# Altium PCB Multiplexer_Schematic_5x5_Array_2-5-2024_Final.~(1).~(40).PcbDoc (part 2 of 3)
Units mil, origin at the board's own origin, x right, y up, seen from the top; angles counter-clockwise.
Board outline 7305 x 4000 mil, 8 copper layers (Loop Shield 1, Loop Trace, Loop Shield 2, GND 1, DC Signal 1, DC Signal 2, GND 2 (RF), RF), stack 74.018 mil thick; 89 components, 122 nets, 436 pads, 3654 vias.
Unrouted connection lines stored in the file: 2.
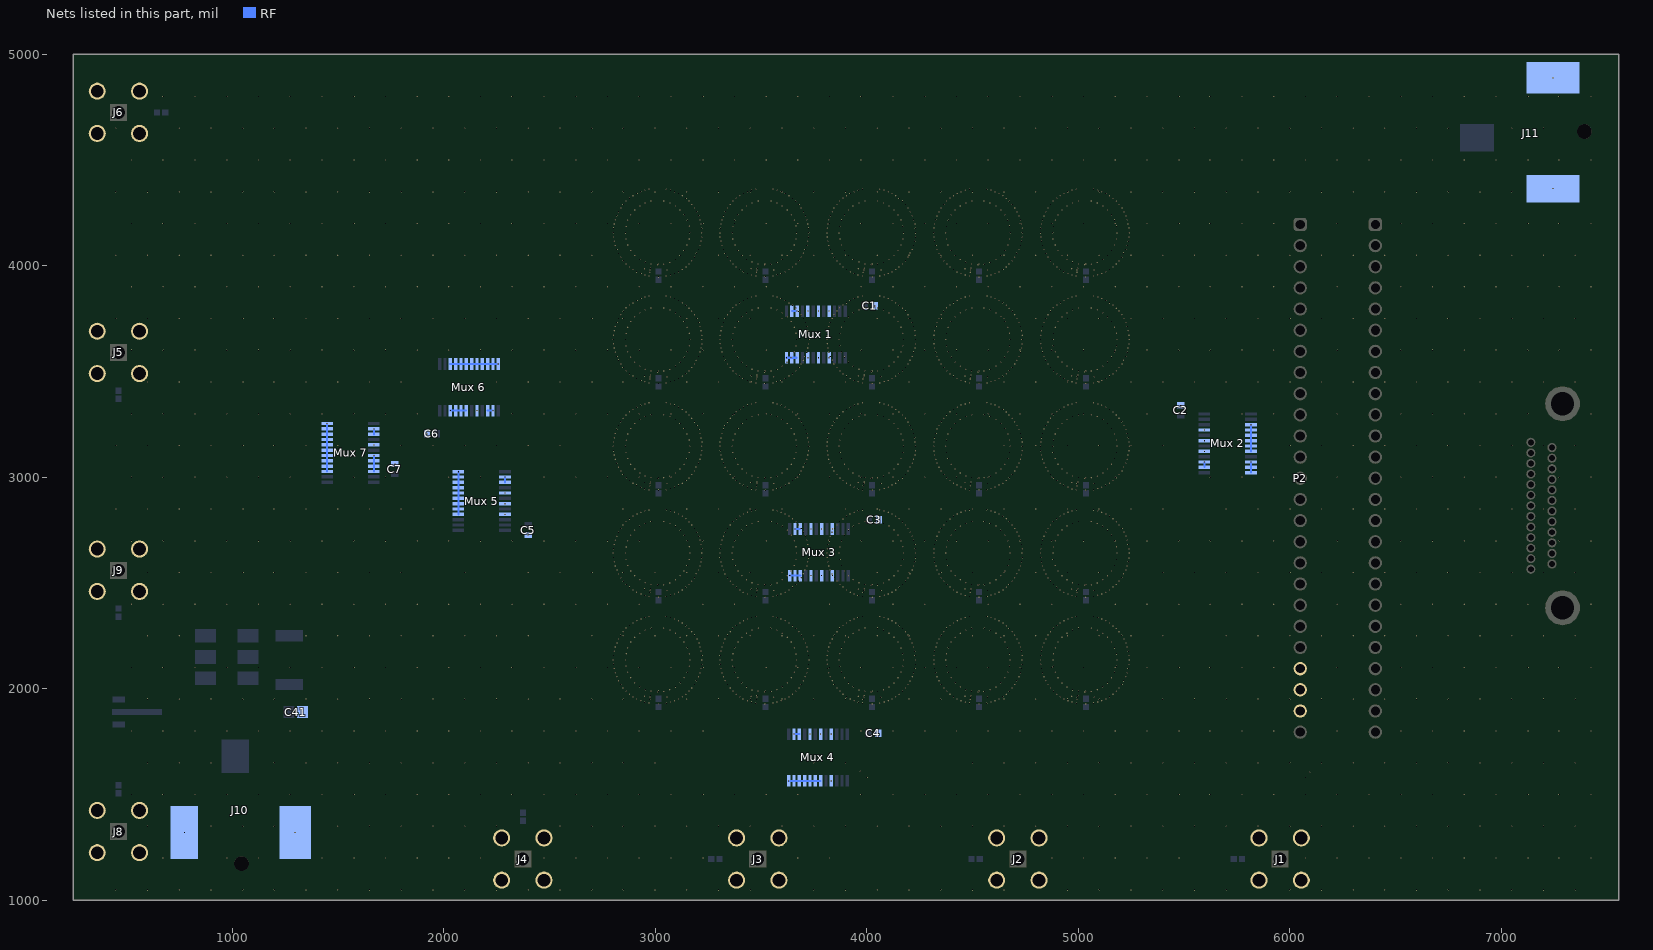
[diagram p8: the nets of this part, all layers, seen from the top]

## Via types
v1: diameter 6, hole 4, Loop Shield 1 to Loop Shield 2, 2300 vias
v2: diameter 6, hole 4, GND 2 (RF) to RF, 1131 vias
v3: diameter 6, hole 4, Loop Shield 2 to RF, 75 vias
v4: diameter 6, hole 4, DC Signal 1 to DC Signal 2, 57 vias
v5: diameter 6, hole 4, DC Signal 1 to RF, 25 vias
v6: diameter 6, hole 4, Loop Shield 2 to GND 2 (RF), 25 vias
v7: diameter 6, hole 4, Loop Trace to RF, 25 vias
v8: diameter 6, hole 4, DC Signal 2 to RF, 16 vias

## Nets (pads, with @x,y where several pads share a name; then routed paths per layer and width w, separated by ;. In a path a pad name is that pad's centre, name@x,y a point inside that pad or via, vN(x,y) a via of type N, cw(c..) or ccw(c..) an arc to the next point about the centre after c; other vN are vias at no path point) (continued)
GND: "Mux 1.2" "Mux 1.3" "Mux 1.5" "Mux 1.7" "Mux 1.9" "Mux 1.16" "Mux 1.18" "Mux 1.20" "Mux 1.22" "Mux 1.23" "Mux 1.24" "Mux 2.2" "Mux 2.3" "Mux 2.5" "Mux 2.7" "Mux 2.9" "Mux 2.15" "Mux 2.16" "Mux 2.17" "Mux 2.18" "Mux 2.19" "Mux 2.20" "Mux 2.22" "Mux 2.23" "Mux 2.24" "Mux 3.2" "Mux 3.3" "Mux 3.5" "Mux 3.7" "Mux 3.9" "Mux 3.16" "Mux 3.18" "Mux 3.20" "Mux 3.22" "Mux 3.23" "Mux 3.24" "Mux 4.2" "Mux 4.3" "Mux 4.5" "Mux 4.7" "Mux 4.9" "Mux 4.16" "Mux 4.18" "Mux 4.19" "Mux 4.20" "Mux 4.21" "Mux 4.22" "Mux 4.23" "Mux 4.24" "Mux 5.2" "Mux 5.3" "Mux 5.5" "Mux 5.7" "Mux 5.9" "Mux 5.16" "Mux 5.17" "Mux 5.18" "Mux 5.19" "Mux 5.20" "Mux 5.21" "Mux 5.22" "Mux 5.23" "Mux 5.24" "Mux 6.2" "Mux 6.3" "Mux 6.5" "Mux 6.7" "Mux 6.8" "Mux 6.9" "Mux 6.10" "Mux 6.15" "Mux 6.16" "Mux 6.17" "Mux 6.18" "Mux 6.19" "Mux 6.20" "Mux 6.21" "Mux 6.22" "Mux 6.23" "Mux 6.24" "Mux 7.2" "Mux 7.3" "Mux 7.5" "Mux 7.7" "Mux 7.8" "Mux 7.9" "Mux 7.10" "Mux 7.15" "Mux 7.16" "Mux 7.17" "Mux 7.18" "Mux 7.19" "Mux 7.20" "Mux 7.21" "Mux 7.22" "Mux 7.23" "Mux 7.24" C1.2 C2.2 C3.2 C4.2 C5.2 C6.2 C7.2 C41.2 J1.2 J1.3 J1.4 J1.5 J2.2 J2.3 J2.4 J2.5 J3.2 J3.3 J3.4 J3.5 J4.2 J4.3 J4.4 J4.5 J5.2 J5.3 J5.4 J5.5 J6.2 J6.3 J6.4 J6.5 J8.2 J8.3 J8.4 J8.5 J9.2 J9.3 J9.4 J9.5 J10.2 J10.3 J11.2 J11.3 P2.22 P2.23 P2.24 | length 1402
  RF w10: 1449.76,3026.81 1449.76,3052.01 1449.76,3077.2 1449.76,3102.4 1449.76,3127.6 1449.76,3152.8 1449.76,3177.99 1449.76,3203.19 1449.76,3228.39 v2(1449.76,3253.58) ; 1670.24,3026.81 1670.24,3052.01 1670.24,3077.2 v2(1670.24,3102.4) ; 1670.24,3203.19 v2(1670.24,3228.39) ; v2(2031.81,3314.76) 2057.01,3314.76 2082.2,3314.76 2106.8,3314.76 ; 2031.81,3535.24 2057.01,3535.24 2082.2,3535.24 2107.4,3535.24 2132.6,3535.24 2157.8,3535.24 2182.99,3535.24 2208.19,3535.24 2233.39,3535.24 v2@2258.58,3535.24 ; 2069.76,2824.38 2069.76,2849.58 2069.76,2874.77 2069.76,2899.97 2069.76,2925.17 2069.76,2950.36 2069.76,2975.56 2069.76,3000.76 v2(2069.76,3025.95) ; 2208.19,3314.76 v2(2233.39,3314.76) ; 2290.24,2975.56 v2(2290.24,3000.76) ; v2(3621.42,3564.76) 3646.61,3564.76 3668.94,3564.76 ; v2(3631.42,1564.76) 3656.61,1564.76 3681.81,1564.76 3707.01,1564.76 3732.2,1564.76 3757.4,1564.76 3782.6,1564.76 ; v2(3636.42,2534.76) 3661.61,2534.76 3686.81,2534.76 ; 3646.61,3785.24 3671.37,3785.24 v2(3671.65,3785.52) ; v2@3658.62,1785.24 3681.81,1785.24 ; v2(3661.61,2755.24) 3683.94,2755.24 ; v2@5595,3070.34 cw(c5596.47,3070.34) v2(5596.47,3071.81) 5596.47,3049.49 ; 5816.94,3021.42 5816.94,3046.61 v2(5816.94,3071.81) ; 5816.94,3122.2 5816.94,3147.4 5816.94,3172.6 5816.94,3197.8 5816.94,3222.99 v2(5816.94,3248.19)
  other v1: 2970.86,1930.81 3052.58,1930.81 3475.86,1930.81 3557.58,1930.81 3980.86,1930.81 4062.58,1930.81 4485.86,1930.81 4567.58,1930.81 4990.86,1930.81 5072.58,1930.81 2950.93,1935.81 3455.93,1935.81 3960.93,1935.81 4465.93,1935.81 4970.93,1935.81 3073.01,1937.21 3578.01,1937.21 4083.01,1937.21 4588.01,1937.21 5093.01,1937.21 2931.57,1942.73 3091.87,1942.73 3436.57,1942.73 3596.87,1942.73 3941.57,1942.73 4101.87,1942.73 4446.57,1942.73 4606.87,1942.73 4951.57,1942.73 5111.87,1942.73 2974.61,1949.63 3479.61,1949.63 3984.61,1949.63 4489.61,1949.63 4994.61,1949.63 2911.98,1951.64 3110.45,1951.52 3416.98,1951.64 3615.45,1951.52 3921.98,1951.64 4120.45,1951.52 4426.98,1951.64 4625.45,1951.52 4931.98,1951.64 5130.45,1951.52 2895.37,1962.08 3128.08,1962.08 3400.37,1962.08 3633.08,1962.08 3905.37,1962.08 4138.08,1962.08 4410.37,1962.08 4643.08,1962.08 4915.37,1962.08 5148.08,1962.08 2950,1965 3455,1965 3960,1965 4465,1965 4970,1965 2978.23,1967.83 3483.23,1967.83 3988.23,1967.83 4493.23,1967.83 4998.23,1967.83 2878.86,1974.33 3144.58,1974.33 3383.86,1974.33 3649.58,1974.33 3888.86,1974.33 4154.58,1974.33 4393.86,1974.33 4659.58,1974.33 4898.86,1974.33 5164.58,1974.33 3011.72,1984.11 3516.72,1984.11 4021.72,1984.11 4526.72,1984.11 5031.72,1984.11 3041.4,1987.04 3546.4,1987.04 4051.4,1987.04 4556.4,1987.04 5061.4,1987.04 2863.63,1988.13 2981.13,1988.15 3159.81,1988.13 3368.63,1988.13 3486.13,1988.15 3664.81,1988.13 3873.63,1988.13 3991.13,1988.15 4169.81,1988.13 4378.63,1988.13 4496.13,1988.15 4674.81,1988.13 4883.63,1988.13 5001.13,1988.15 5179.81,1988.13 3069.84,1994.62 3574.84,1994.62 4079.84,1994.62 4584.84,1994.62 5089.84,1994.62 2953.51,1995.69 3458.51,1995.69 3963.51,1995.69 4468.51,1995.69 4973.51,1995.69 2849.83,2003.36 3173.61,2003.36 3354.83,2003.36 3678.61,2003.36 3859.83,2003.36 4183.61,2003.36 4364.83,2003.36 4688.61,2003.36 4869.83,2003.36 5193.61,2003.36 2927.21,2009.75 3096.23,2009.75 3432.21,2009.75 3601.23,2009.75 3937.21,2009.75 4106.23,2009.75 4442.21,2009.75 4611.23,2009.75 4947.21,2009.75 5116.23,2009.75 2837.58,2019.87 3185.86,2019.87 3342.58,2019.87 3690.86,2019.87 3847.58,2019.87 4195.86,2019.87 4352.58,2019.87 4700.86,2019.87 4857.58,2019.87 5205.86,2019.87 2904.17,2028.67 3119.28,2028.67 3409.17,2028.67 3624.28,2028.67 3914.17,2028.67 4129.28,2028.67 4419.17,2028.67 4634.28,2028.67 4924.17,2028.67 5139.28,2028.67 2827.02,2037.49 3332.02,2037.49 3837.02,2037.49 4342.02,2037.49 4847.02,2037.49 3194.83,2038.24 3699.83,2038.24 4204.83,2038.24 4709.83,2038.24 5214.83,2038.24 2885.25,2051.71 3138.19,2051.71 3390.25,2051.71 3643.19,2051.71 3895.25,2051.71 4148.19,2051.71 4400.25,2051.71 4653.19,2051.71 4905.25,2051.71 5158.19,2051.71 2818.23,2056.07 3205.21,2056.07 3323.23,2056.07 3710.21,2056.07 3828.23,2056.07 4215.21,2056.07 4333.23,2056.07 4720.21,2056.07 4838.23,2056.07 5225.21,2056.07 2811.31,2075.43 3212.14,2075.43 3316.31,2075.43 3717.14,2075.43 3821.31,2075.43 4222.14,2075.43 4326.31,2075.43 4727.14,2075.43 4831.31,2075.43 5232.14,2075.43 2871.19,2078.01 3152.25,2078.01 3376.19,2078.01 3657.25,2078.01 3881.19,2078.01 4162.25,2078.01 4386.19,2078.01 4667.25,2078.01 4891.19,2078.01 5172.25,2078.01 2806.31,2095.36 3217.13,2095.36 3311.31,2095.36 3722.13,2095.36 3816.31,2095.36 4227.13,2095.36 4321.31,2095.36 4732.13,2095.36 4826.31,2095.36 5237.13,2095.36 2862.54,2106.55 3160.9,2106.55 3367.54,2106.55 3665.9,2106.55 3872.54,2106.55 4170.9,2106.55 4377.54,2106.55 4675.9,2106.55 4882.54,2106.55 5180.9,2106.55 3220.6,2114.62 3725.6,2114.62 4230.6,2114.62 4735.6,2114.62 5240.6,2114.62 2803.3,2115.69 3308.3,2115.69 3813.3,2115.69 4318.3,2115.69 4823.3,2115.69 2802.29,2136.22 2859.61,2136.22 3163.83,2136.22 3221.15,2136.22 3307.29,2136.22 3364.61,2136.22 3668.83,2136.22 3726.15,2136.22 3812.29,2136.22 3869.61,2136.22 4173.83,2136.22 4231.15,2136.22 4317.29,2136.22 4374.61,2136.22 4678.83,2136.22 4736.15,2136.22 4822.29,2136.22 4879.61,2136.22 5183.83,2136.22 5241.15,2136.22 2803.3,2156.75 3220.14,2156.75 3308.3,2156.75 3725.14,2156.75 3813.3,2156.75 4230.14,2156.75 4318.3,2156.75 4735.14,2156.75 4823.3,2156.75 5240.14,2156.75 2863.04,2164.95 3368.04,2164.95 3873.04,2164.95 4378.04,2164.95 4883.04,2164.95 3160.9,2165.9 3665.9,2165.9 4170.9,2165.9 4675.9,2165.9 5180.9,2165.9 2806.31,2177.08 3217.13,2177.08 3311.31,2177.08 3722.13,2177.08 3816.31,2177.08 4227.13,2177.08 4321.31,2177.08 4732.13,2177.08 4826.31,2177.08 5237.13,2177.08 2871.19,2194.43 3152.25,2194.43 3376.19,2194.43 3657.25,2194.43 3881.19,2194.43 4162.25,2194.43 4386.19,2194.43 4667.25,2194.43 4891.19,2194.43 5172.25,2194.43 2811.31,2197.02 3212.14,2197.02 3316.31,2197.02 3717.14,2197.02 3821.31,2197.02 4222.14,2197.02 4326.31,2197.02 4727.14,2197.02 4831.31,2197.02 5232.14,2197.02 2818.23,2216.37 3205.9,2216.15 3323.23,2216.37 3710.9,2216.15 3828.23,2216.37 4215.9,2216.15 4333.23,2216.37 4720.9,2216.15 4838.23,2216.37 5225.9,2216.15 2885.25,2220.73 3138.19,2220.73 3390.25,2220.73 3643.19,2220.73 3895.25,2220.73 4148.19,2220.73 4400.25,2220.73 4653.19,2220.73 4905.25,2220.73 5158.19,2220.73 2827.02,2234.95 3196.42,2234.95 3332.02,2234.95 3701.42,2234.95 3837.02,2234.95 4206.42,2234.95 4342.02,2234.95 4711.42,2234.95 4847.02,2234.95 5216.42,2234.95 2904.17,2243.78 3119.28,2243.78 3409.17,2243.78 3624.28,2243.78 3914.17,2243.78 4129.28,2243.78 4419.17,2243.78 4634.28,2243.78 4924.17,2243.78 5139.28,2243.78 2837.58,2252.58 3185.86,2252.58 3342.58,2252.58 3690.86,2252.58 3847.58,2252.58 4195.86,2252.58 4352.58,2252.58 4700.86,2252.58 4857.58,2252.58 5205.86,2252.58 2927.21,2262.69 3096.23,2262.69 3432.21,2262.69 3601.23,2262.69 3937.21,2262.69 4106.23,2262.69 4442.21,2262.69 4611.23,2262.69 4947.21,2262.69 5116.23,2262.69 2849.83,2269.08 3173.61,2269.08 3354.83,2269.08 3678.61,2269.08 3859.83,2269.08 4183.61,2269.08 4364.83,2269.08 4688.61,2269.08 4869.83,2269.08 5193.61,2269.08 2953.51,2276.75 3069.93,2276.75 3458.51,2276.75 3574.93,2276.75 3963.51,2276.75 4079.93,2276.75 4468.51,2276.75 4584.93,2276.75 4973.51,2276.75 5089.93,2276.75 3159.81,2284.31 3664.81,2284.31 4169.81,2284.31 4674.81,2284.31 5179.81,2284.31 2982.05,2285.4 3041.4,2285.4 3487.05,2285.4 3546.4,2285.4 3992.05,2285.4 4051.4,2285.4 4497.05,2285.4 4556.4,2285.4 5002.05,2285.4 5061.4,2285.4 2862.23,2285.59 3367.23,2285.59 3872.23,2285.59 4377.23,2285.59 4882.23,2285.59 3144.58,2298.11 3649.58,2298.11 4154.58,2298.11 4659.58,2298.11 5164.58,2298.11 2878.77,2299.07 3383.77,2299.07 3888.77,2299.07 4393.77,2299.07 4898.77,2299.07 2895.37,2310.36 3128.08,2310.36 3400.37,2310.36 3633.08,2310.36 3905.37,2310.36 4138.08,2310.36 4410.37,2310.36 4643.08,2310.36 4915.37,2310.36 5148.08,2310.36 2912.99,2320.92 3110.45,2320.92 3417.99,2320.92 3615.45,2320.92 3922.99,2320.92 4120.45,2320.92 4427.99,2320.92 4625.45,2320.92 4932.99,2320.92 5130.45,2320.92 2931.57,2329.71 3091.87,2329.71 3436.57,2329.71 3596.87,2329.71 3941.57,2329.71 4101.87,2329.71 4446.57,2329.71 4606.87,2329.71 4951.57,2329.71 5111.87,2329.71 2950.93,2336.64 3072.52,2336.64 3455.93,2336.64 3577.52,2336.64 3960.93,2336.64 4082.52,2336.64 4465.93,2336.64 4587.52,2336.64 4970.93,2336.64 5092.52,2336.64 2970.86,2341.63 3052.58,2341.63 3475.86,2341.63 3557.58,2341.63 3980.86,2341.63 4062.58,2341.63 4485.86,2341.63 4567.58,2341.63 4990.86,2341.63 5072.58,2341.63 2970.86,2435.81 3052.58,2435.81 3475.86,2435.81 3557.58,2435.81 3980.86,2435.81 4062.58,2435.81 4485.86,2435.81 4567.58,2435.81 4990.86,2435.81 5072.58,2435.81 2950.93,2440.81 3455.93,2440.81 3960.93,2440.81 4465.93,2440.81 4970.93,2440.81 3073.01,2442.21 3578.01,2442.21 4083.01,2442.21 4588.01,2442.21 5093.01,2442.21 2931.57,2447.73 3091.87,2447.73 3436.57,2447.73 3596.87,2447.73 3941.57,2447.73 4101.87,2447.73 4446.57,2447.73 4606.87,2447.73 4951.57,2447.73 5111.87,2447.73 2974.61,2454.63 3479.61,2454.63 3984.61,2454.63 4489.61,2454.63 4994.61,2454.63 2911.98,2456.64 3110.45,2456.52 3416.98,2456.64 3615.45,2456.52 3921.98,2456.64 4120.45,2456.52 4426.98,2456.64 4625.45,2456.52 4931.98,2456.64 5130.45,2456.52 2895.37,2467.08 3128.08,2467.08 3400.37,2467.08 3633.08,2467.08 3905.37,2467.08 4138.08,2467.08 4410.37,2467.08 4643.08,2467.08 4915.37,2467.08 5148.08,2467.08 2950,2470 3455,2470 3960,2470 4465,2470 4970,2470 2978.23,2472.83 3483.23,2472.83 3988.23,2472.83 4493.23,2472.83 4998.23,2472.83 2878.86,2479.33 3144.58,2479.33 3383.86,2479.33 3649.58,2479.33 3888.86,2479.33 4154.58,2479.33 4393.86,2479.33 4659.58,2479.33 4898.86,2479.33 5164.58,2479.33 3011.72,2489.11 3516.72,2489.11 4021.72,2489.11 4526.72,2489.11 5031.72,2489.11 3041.4,2492.04 3546.4,2492.04 4051.4,2492.04 4556.4,2492.04 5061.4,2492.04 2863.63,2493.13 2981.13,2493.15 3159.81,2493.13 3368.63,2493.13 3486.13,2493.15 3664.81,2493.13 3873.63,2493.13 3991.13,2493.15 4169.81,2493.13 4378.63,2493.13 4496.13,2493.15 4674.81,2493.13 4883.63,2493.13 5001.13,2493.15 5179.81,2493.13 3069.84,2499.62 3574.84,2499.62 4079.84,2499.62 4584.84,2499.62 5089.84,2499.62 2953.51,2500.69 3458.51,2500.69 3963.51,2500.69 4468.51,2500.69 4973.51,2500.69 2849.83,2508.36 3173.61,2508.36 3354.83,2508.36 3678.61,2508.36 3859.83,2508.36 4183.61,2508.36 4364.83,2508.36 4688.61,2508.36 4869.83,2508.36 5193.61,2508.36 2927.21,2514.75 3096.23,2514.75 3432.21,2514.75 3601.23,2514.75 3937.21,2514.75 4106.23,2514.75 4442.21,2514.75 4611.23,2514.75 4947.21,2514.75 5116.23,2514.75 2837.58,2524.87 3185.86,2524.87 3342.58,2524.87 3690.86,2524.87 3847.58,2524.87 4195.86,2524.87 4352.58,2524.87 4700.86,2524.87 4857.58,2524.87 5205.86,2524.87 2904.17,2533.67 3119.28,2533.67 3409.17,2533.67 3624.28,2533.67 3914.17,2533.67 4129.28,2533.67 4419.17,2533.67 4634.28,2533.67 4924.17,2533.67 5139.28,2533.67 2827.02,2542.49 3332.02,2542.49 3837.02,2542.49 4342.02,2542.49 4847.02,2542.49 3194.83,2543.24 3699.83,2543.24 4204.83,2543.24 4709.83,2543.24 5214.83,2543.24 2885.25,2556.71 3138.19,2556.71 3390.25,2556.71 3643.19,2556.71 3895.25,2556.71 4148.19,2556.71 4400.25,2556.71 4653.19,2556.71 4905.25,2556.71 5158.19,2556.71 2818.23,2561.07 3205.21,2561.07 3323.23,2561.07 3710.21,2561.07 3828.23,2561.07 4215.21,2561.07 4333.23,2561.07 4720.21,2561.07 4838.23,2561.07 5225.21,2561.07 2811.31,2580.43 3212.14,2580.43 3316.31,2580.43 3717.14,2580.43 3821.31,2580.43 4222.14,2580.43 4326.31,2580.43 4727.14,2580.43 4831.31,2580.43 5232.14,2580.43 2871.19,2583.01 3152.25,2583.01 3376.19,2583.01 3657.25,2583.01 3881.19,2583.01 4162.25,2583.01 4386.19,2583.01 4667.25,2583.01 4891.19,2583.01 5172.25,2583.01 2806.31,2600.36 3217.13,2600.36 3311.31,2600.36 3722.13,2600.36 3816.31,2600.36 4227.13,2600.36 4321.31,2600.36 4732.13,2600.36 4826.31,2600.36 5237.13,2600.36 2862.54,2611.55 3160.9,2611.55 3367.54,2611.55 3665.9,2611.55 3872.54,2611.55 4170.9,2611.55 4377.54,2611.55 4675.9,2611.55 4882.54,2611.55 5180.9,2611.55 3220.6,2619.62 3725.6,2619.62 4230.6,2619.62 4735.6,2619.62 5240.6,2619.62 2803.3,2620.69 3308.3,2620.69 3813.3,2620.69 4318.3,2620.69 4823.3,2620.69 2802.29,2641.22 2859.61,2641.22 3163.83,2641.22 3221.15,2641.22 3307.29,2641.22 3364.61,2641.22 3668.83,2641.22 3726.15,2641.22 3812.29,2641.22 3869.61,2641.22 4173.83,2641.22 4231.15,2641.22 4317.29,2641.22 4374.61,2641.22 4678.83,2641.22 4736.15,2641.22 4822.29,2641.22 4879.61,2641.22 5183.83,2641.22 5241.15,2641.22 2803.3,2661.75 3220.14,2661.75 3308.3,2661.75 3725.14,2661.75 3813.3,2661.75 4230.14,2661.75 4318.3,2661.75 4735.14,2661.75 4823.3,2661.75 5240.14,2661.75 2863.04,2669.95 3368.04,2669.95 3873.04,2669.95 4378.04,2669.95 4883.04,2669.95 3160.9,2670.9 3665.9,2670.9 4170.9,2670.9 4675.9,2670.9 5180.9,2670.9 2806.31,2682.08 3217.13,2682.08 3311.31,2682.08 3722.13,2682.08 3816.31,2682.08 4227.13,2682.08 4321.31,2682.08 4732.13,2682.08 4826.31,2682.08 5237.13,2682.08 2871.19,2699.43 3152.25,2699.43 3376.19,2699.43 3657.25,2699.43 3881.19,2699.43 4162.25,2699.43 4386.19,2699.43 4667.25,2699.43 4891.19,2699.43 5172.25,2699.43 2811.31,2702.02 3212.14,2702.02 3316.31,2702.02 3717.14,2702.02 3821.31,2702.02 4222.14,2702.02 4326.31,2702.02 4727.14,2702.02 4831.31,2702.02 5232.14,2702.02 2818.23,2721.37 3205.9,2721.15 3323.23,2721.37 3710.9,2721.15 3828.23,2721.37 4215.9,2721.15 4333.23,2721.37 4720.9,2721.15 4838.23,2721.37 5225.9,2721.15 2885.25,2725.73 3138.19,2725.73 3390.25,2725.73 3643.19,2725.73 3895.25,2725.73 4148.19,2725.73 4400.25,2725.73 4653.19,2725.73 4905.25,2725.73 5158.19,2725.73 2827.02,2739.95 3196.42,2739.95 3332.02,2739.95 3701.42,2739.95 3837.02,2739.95 4206.42,2739.95 4342.02,2739.95 4711.42,2739.95 4847.02,2739.95 5216.42,2739.95 2904.17,2748.78 3119.28,2748.78 3409.17,2748.78 3624.28,2748.78 3914.17,2748.78 4129.28,2748.78 4419.17,2748.78 4634.28,2748.78 4924.17,2748.78 5139.28,2748.78 2837.58,2757.58 3185.86,2757.58 3342.58,2757.58 3690.86,2757.58 3847.58,2757.58 4195.86,2757.58 4352.58,2757.58 4700.86,2757.58 4857.58,2757.58 5205.86,2757.58 2927.21,2767.69 3096.23,2767.69 3432.21,2767.69 3601.23,2767.69 3937.21,2767.69 4106.23,2767.69 4442.21,2767.69 4611.23,2767.69 4947.21,2767.69 5116.23,2767.69 2849.83,2774.08 3173.61,2774.08 3354.83,2774.08 3678.61,2774.08 3859.83,2774.08 4183.61,2774.08 4364.83,2774.08 4688.61,2774.08 4869.83,2774.08 5193.61,2774.08 2953.51,2781.75 3069.93,2781.75 3458.51,2781.75 3574.93,2781.75 3963.51,2781.75 4079.93,2781.75 4468.51,2781.75 4584.93,2781.75 4973.51,2781.75 5089.93,2781.75 3159.81,2789.31 3664.81,2789.31 4169.81,2789.31 4674.81,2789.31 5179.81,2789.31 2982.05,2790.4 3041.4,2790.4 3487.05,2790.4 3546.4,2790.4 3992.05,2790.4 4051.4,2790.4 4497.05,2790.4 4556.4,2790.4 5002.05,2790.4 5061.4,2790.4 2862.23,2790.59 3367.23,2790.59 3872.23,2790.59 4377.23,2790.59 4882.23,2790.59 3144.58,2803.11 3649.58,2803.11 4154.58,2803.11 4659.58,2803.11 5164.58,2803.11 2878.77,2804.07 3383.77,2804.07 3888.77,2804.07 4393.77,2804.07 4898.77,2804.07 2895.37,2815.36 3128.08,2815.36 3400.37,2815.36 3633.08,2815.36 3905.37,2815.36 4138.08,2815.36 4410.37,2815.36 4643.08,2815.36 4915.37,2815.36 5148.08,2815.36 2912.99,2825.92 3110.45,2825.92 3417.99,2825.92 3615.45,2825.92 3922.99,2825.92 4120.45,2825.92 4427.99,2825.92 4625.45,2825.92 4932.99,2825.92 5130.45,2825.92 2931.57,2834.71 3091.87,2834.71 3436.57,2834.71 3596.87,2834.71 3941.57,2834.71 4101.87,2834.71 4446.57,2834.71 4606.87,2834.71 4951.57,2834.71 5111.87,2834.71 2950.93,2841.64 3072.52,2841.64 3455.93,2841.64 3577.52,2841.64 3960.93,2841.64 4082.52,2841.64 4465.93,2841.64 4587.52,2841.64 4970.93,2841.64 5092.52,2841.64 2970.86,2846.63 3052.58,2846.63 3475.86,2846.63 3557.58,2846.63 3980.86,2846.63 4062.58,2846.63 4485.86,2846.63 4567.58,2846.63 4990.86,2846.63 5072.58,2846.63 2970.86,2940.81 3052.58,2940.81 3475.86,2940.81 3557.58,2940.81 3980.86,2940.81 4062.58,2940.81 4485.86,2940.81 4567.58,2940.81 4990.86,2940.81 5072.58,2940.81 2950.93,2945.81 3455.93,2945.81 3960.93,2945.81 4465.93,2945.81 4970.93,2945.81 3073.01,2947.21 3578.01,2947.21 4083.01,2947.21 4588.01,2947.21 5093.01,2947.21 2931.57,2952.73 3091.87,2952.73 3436.57,2952.73 3596.87,2952.73 3941.57,2952.73 4101.87,2952.73 4446.57,2952.73 4606.87,2952.73 4951.57,2952.73 5111.87,2952.73 2974.61,2959.63 3479.61,2959.63 3984.61,2959.63 4489.61,2959.63 4994.61,2959.63 2911.98,2961.64 3110.45,2961.52 3416.98,2961.64 3615.45,2961.52 3921.98,2961.64 4120.45,2961.52 4426.98,2961.64 4625.45,2961.52 4931.98,2961.64 5130.45,2961.52 2895.37,2972.08 3128.08,2972.08 3400.37,2972.08 3633.08,2972.08 3905.37,2972.08 4138.08,2972.08 4410.37,2972.08 4643.08,2972.08 4915.37,2972.08 5148.08,2972.08 2950,2975 3455,2975 3960,2975 4465,2975 4970,2975 2978.23,2977.83 3483.23,2977.83 3988.23,2977.83 4493.23,2977.83 4998.23,2977.83 2878.86,2984.33 3144.58,2984.33 3383.86,2984.33 3649.58,2984.33 3888.86,2984.33 4154.58,2984.33 4393.86,2984.33 4659.58,2984.33 4898.86,2984.33 5164.58,2984.33 3011.72,2994.11 3516.72,2994.11 4021.72,2994.11 4526.72,2994.11 5031.72,2994.11 3041.4,2997.04 3546.4,2997.04 4051.4,2997.04 4556.4,2997.04 5061.4,2997.04 2863.63,2998.13 2981.13,2998.15 3159.81,2998.13 3368.63,2998.13 3486.13,2998.15 3664.81,2998.13 3873.63,2998.13 3991.13,2998.15 4169.81,2998.13 4378.63,2998.13 4496.13,2998.15 4674.81,2998.13 4883.63,2998.13 5001.13,2998.15 5179.81,2998.13 3069.84,3004.62 3574.84,3004.62 4079.84,3004.62 4584.84,3004.62 5089.84,3004.62 2953.51,3005.69 3458.51,3005.69 3963.51,3005.69 4468.51,3005.69 4973.51,3005.69 2849.83,3013.36 3173.61,3013.36 3354.83,3013.36 3678.61,3013.36 3859.83,3013.36 4183.61,3013.36 4364.83,3013.36 4688.61,3013.36 4869.83,3013.36 5193.61,3013.36 2927.21,3019.75 3096.23,3019.75 3432.21,3019.75 3601.23,3019.75 3937.21,3019.75 4106.23,3019.75 4442.21,3019.75 4611.23,3019.75 4947.21,3019.75 5116.23,3019.75 2837.58,3029.87 3185.86,3029.87 3342.58,3029.87 3690.86,3029.87 3847.58,3029.87 4195.86,3029.87 4352.58,3029.87 4700.86,3029.87 4857.58,3029.87 5205.86,3029.87 2904.17,3038.67 3119.28,3038.67 3409.17,3038.67 3624.28,3038.67 3914.17,3038.67 4129.28,3038.67 4419.17,3038.67 4634.28,3038.67 4924.17,3038.67 5139.28,3038.67 2827.02,3047.49 3332.02,3047.49 3837.02,3047.49 4342.02,3047.49 4847.02,3047.49 3194.83,3048.24 3699.83,3048.24 4204.83,3048.24 4709.83,3048.24 5214.83,3048.24 2885.25,3061.71 3138.19,3061.71 3390.25,3061.71 3643.19,3061.71 3895.25,3061.71 4148.19,3061.71 4400.25,3061.71 4653.19,3061.71 4905.25,3061.71 5158.19,3061.71 2818.23,3066.07 3205.21,3066.07 3323.23,3066.07 3710.21,3066.07 3828.23,3066.07 4215.21,3066.07 4333.23,3066.07 4720.21,3066.07 4838.23,3066.07 5225.21,3066.07 2811.31,3085.43 3212.14,3085.43 3316.31,3085.43 3717.14,3085.43 3821.31,3085.43 4222.14,3085.43 4326.31,3085.43 4727.14,3085.43 4831.31,3085.43 5232.14,3085.43 2871.19,3088.01 3152.25,3088.01 3376.19,3088.01 3657.25,3088.01 3881.19,3088.01 4162.25,3088.01 4386.19,3088.01 4667.25,3088.01 4891.19,3088.01 5172.25,3088.01 2806.31,3105.36 3217.13,3105.36 3311.31,3105.36 3722.13,3105.36 3816.31,3105.36 4227.13,3105.36 4321.31,3105.36 4732.13,3105.36 4826.31,3105.36 5237.13,3105.36 2862.54,3116.55 3160.9,3116.55 3367.54,3116.55 3665.9,3116.55 3872.54,3116.55 4170.9,3116.55 4377.54,3116.55 4675.9,3116.55 4882.54,3116.55 5180.9,3116.55 3220.6,3124.62 3725.6,3124.62 4230.6,3124.62 4735.6,3124.62 5240.6,3124.62 2803.3,3125.69 3308.3,3125.69 3813.3,3125.69 4318.3,3125.69 4823.3,3125.69 2802.29,3146.22 2859.61,3146.22 3163.83,3146.22 3221.15,3146.22 3307.29,3146.22 3364.61,3146.22 3668.83,3146.22 3726.15,3146.22 3812.29,3146.22 3869.61,3146.22 4173.83,3146.22 4231.15,3146.22 4317.29,3146.22 4374.61,3146.22 4678.83,3146.22 4736.15,3146.22 4822.29,3146.22 4879.61,3146.22 5183.83,3146.22 5241.15,3146.22 2803.3,3166.75 3220.14,3166.75 3308.3,3166.75 3725.14,3166.75 3813.3,3166.75 4230.14,3166.75 4318.3,3166.75 4735.14,3166.75 4823.3,3166.75 5240.14,3166.75 2863.04,3174.95 3368.04,3174.95 3873.04,3174.95 4378.04,3174.95 4883.04,3174.95 3160.9,3175.9 3665.9,3175.9 4170.9,3175.9 4675.9,3175.9 5180.9,3175.9 2806.31,3187.08 3217.13,3187.08 3311.31,3187.08 3722.13,3187.08 3816.31,3187.08 4227.13,3187.08 4321.31,3187.08 4732.13,3187.08 4826.31,3187.08 5237.13,3187.08 2871.19,3204.43 3152.25,3204.43 3376.19,3204.43 3657.25,3204.43 3881.19,3204.43 4162.25,3204.43 4386.19,3204.43 4667.25,3204.43 4891.19,3204.43 5172.25,3204.43 2811.31,3207.02 3212.14,3207.02 3316.31,3207.02 3717.14,3207.02 3821.31,3207.02 4222.14,3207.02 4326.31,3207.02 4727.14,3207.02 4831.31,3207.02 5232.14,3207.02 2818.23,3226.37 3205.9,3226.15 3323.23,3226.37 3710.9,3226.15 3828.23,3226.37 4215.9,3226.15 4333.23,3226.37 4720.9,3226.15 4838.23,3226.37 5225.9,3226.15 2885.25,3230.73 3138.19,3230.73 3390.25,3230.73 3643.19,3230.73 3895.25,3230.73 4148.19,3230.73 4400.25,3230.73 4653.19,3230.73 4905.25,3230.73 5158.19,3230.73 2827.02,3244.95 3196.42,3244.95 3332.02,3244.95 3701.42,3244.95 3837.02,3244.95 4206.42,3244.95 4342.02,3244.95 4711.42,3244.95 4847.02,3244.95 5216.42,3244.95 2904.17,3253.78 3119.28,3253.78 3409.17,3253.78 3624.28,3253.78 3914.17,3253.78 4129.28,3253.78 4419.17,3253.78 4634.28,3253.78 4924.17,3253.78 5139.28,3253.78 2837.58,3262.58 3185.86,3262.58 3342.58,3262.58 3690.86,3262.58 3847.58,3262.58 4195.86,3262.58 4352.58,3262.58 4700.86,3262.58 4857.58,3262.58 5205.86,3262.58 2927.21,3272.69 3096.23,3272.69 3432.21,3272.69 3601.23,3272.69 3937.21,3272.69 4106.23,3272.69 4442.21,3272.69 4611.23,3272.69 4947.21,3272.69 5116.23,3272.69 2849.83,3279.08 3173.61,3279.08 3354.83,3279.08 3678.61,3279.08 3859.83,3279.08 4183.61,3279.08 4364.83,3279.08 4688.61,3279.08 4869.83,3279.08 5193.61,3279.08 2953.51,3286.75 3069.93,3286.75 3458.51,3286.75 3574.93,3286.75 3963.51,3286.75 4079.93,3286.75 4468.51,3286.75 4584.93,3286.75 4973.51,3286.75 5089.93,3286.75 3159.81,3294.31 3664.81,3294.31 4169.81,3294.31 4674.81,3294.31 5179.81,3294.31 2982.05,3295.4 3041.4,3295.4 3487.05,3295.4 3546.4,3295.4 3992.05,3295.4 4051.4,3295.4 4497.05,3295.4 4556.4,3295.4 5002.05,3295.4 5061.4,3295.4 2862.23,3295.59 3367.23,3295.59 3872.23,3295.59 4377.23,3295.59 4882.23,3295.59 3144.58,3308.11 3649.58,3308.11 4154.58,3308.11 4659.58,3308.11 5164.58,3308.11 2878.77,3309.07 3383.77,3309.07 3888.77,3309.07 4393.77,3309.07 4898.77,3309.07 2895.37,3320.36 3128.08,3320.36 3400.37,3320.36 3633.08,3320.36 3905.37,3320.36 4138.08,3320.36 4410.37,3320.36 4643.08,3320.36 4915.37,3320.36 5148.08,3320.36 2912.99,3330.92 3110.45,3330.92 3417.99,3330.92 3615.45,3330.92 3922.99,3330.92 4120.45,3330.92 4427.99,3330.92 4625.45,3330.92 4932.99,3330.92 5130.45,3330.92 2931.57,3339.71 3091.87,3339.71 3436.57,3339.71 3596.87,3339.71 3941.57,3339.71 4101.87,3339.71 4446.57,3339.71 4606.87,3339.71 4951.57,3339.71 5111.87,3339.71 2950.93,3346.64 3072.52,3346.64 3455.93,3346.64 3577.52,3346.64 3960.93,3346.64 4082.52,3346.64 4465.93,3346.64 4587.52,3346.64 4970.93,3346.64 5092.52,3346.64 2970.86,3351.63 3052.58,3351.63 3475.86,3351.63 3557.58,3351.63 3980.86,3351.63 4062.58,3351.63 4485.86,3351.63 4567.58,3351.63 4990.86,3351.63 5072.58,3351.63 2970.86,3445.81 3052.58,3445.81 3475.86,3445.81 3557.58,3445.81 3980.86,3445.81 4062.58,3445.81 4485.86,3445.81 4567.58,3445.81 4990.86,3445.81 5072.58,3445.81 2950.93,3450.81 3455.93,3450.81 3960.93,3450.81 4465.93,3450.81 4970.93,3450.81 3073.01,3452.21 3578.01,3452.21 4083.01,3452.21 4588.01,3452.21 5093.01,3452.21 2931.57,3457.73 3091.87,3457.73 3436.57,3457.73 3596.87,3457.73 3941.57,3457.73 4101.87,3457.73 4446.57,3457.73 4606.87,3457.73 4951.57,3457.73 5111.87,3457.73 2974.61,3464.63 3479.61,3464.63 3984.61,3464.63 4489.61,3464.63 4994.61,3464.63 2911.98,3466.64 3110.45,3466.52 3416.98,3466.64 3615.45,3466.52 3921.98,3466.64 4120.45,3466.52 4426.98,3466.64 4625.45,3466.52 4931.98,3466.64 5130.45,3466.52 2895.37,3477.08 3128.08,3477.08 3400.37,3477.08 3633.08,3477.08 3905.37,3477.08 4138.08,3477.08 4410.37,3477.08 4643.08,3477.08 4915.37,3477.08 5148.08,3477.08 2950,3480 3455,3480 3960,3480 4465,3480 4970,3480 2978.23,3482.83 3483.23,3482.83 3988.23,3482.83 4493.23,3482.83 4998.23,3482.83 2878.86,3489.33 3144.58,3489.33 3383.86,3489.33 3649.58,3489.33 3888.86,3489.33 4154.58,3489.33 4393.86,3489.33 4659.58,3489.33 4898.86,3489.33 5164.58,3489.33 3011.72,3499.11 3516.72,3499.11 4021.72,3499.11 4526.72,3499.11 5031.72,3499.11 3041.4,3502.04 3546.4,3502.04 4051.4,3502.04 4556.4,3502.04 5061.4,3502.04 2863.63,3503.13 2981.13,3503.15 3159.81,3503.13 3368.63,3503.13 3486.13,3503.15 3664.81,3503.13 3873.63,3503.13 3991.13,3503.15 4169.81,3503.13 4378.63,3503.13 4496.13,3503.15 4674.81,3503.13 4883.63,3503.13 5001.13,3503.15 5179.81,3503.13 3069.84,3509.62 3574.84,3509.62 4079.84,3509.62 4584.84,3509.62 5089.84,3509.62 2953.51,3510.69 3458.51,3510.69 3963.51,3510.69 4468.51,3510.69 4973.51,3510.69 2849.83,3518.36 3173.61,3518.36 3354.83,3518.36 3678.61,3518.36 3859.83,3518.36 4183.61,3518.36 4364.83,3518.36 4688.61,3518.36 4869.83,3518.36 5193.61,3518.36 2927.21,3524.75 3096.23,3524.75 3432.21,3524.75 3601.23,3524.75 3937.21,3524.75 4106.23,3524.75 4442.21,3524.75 4611.23,3524.75 4947.21,3524.75 5116.23,3524.75 2837.58,3534.87 3185.86,3534.87 3342.58,3534.87 3690.86,3534.87 3847.58,3534.87 4195.86,3534.87 4352.58,3534.87 4700.86,3534.87 4857.58,3534.87 5205.86,3534.87 2904.17,3543.67 3119.28,3543.67 3409.17,3543.67 3624.28,3543.67 3914.17,3543.67 4129.28,3543.67 4419.17,3543.67 4634.28,3543.67 4924.17,3543.67 5139.28,3543.67 2827.02,3552.49 3332.02,3552.49 3837.02,3552.49 4342.02,3552.49 4847.02,3552.49 3194.83,3553.24 3699.83,3553.24 4204.83,3553.24 4709.83,3553.24 5214.83,3553.24 2885.25,3566.71 3138.19,3566.71 3390.25,3566.71 3643.19,3566.71 3895.25,3566.71 4148.19,3566.71 4400.25,3566.71 4653.19,3566.71 4905.25,3566.71 5158.19,3566.71 2818.23,3571.07 3205.21,3571.07 3323.23,3571.07 3710.21,3571.07 3828.23,3571.07 4215.21,3571.07 4333.23,3571.07 4720.21,3571.07 4838.23,3571.07 5225.21,3571.07 2811.31,3590.43 3212.14,3590.43 3316.31,3590.43 3717.14,3590.43 3821.31,3590.43 4222.14,3590.43 4326.31,3590.43 4727.14,3590.43 4831.31,3590.43 5232.14,3590.43 2871.19,3593.01 3152.25,3593.01 3376.19,3593.01 3657.25,3593.01 3881.19,3593.01 4162.25,3593.01 4386.19,3593.01 4667.25,3593.01 4891.19,3593.01 5172.25,3593.01 2806.31,3610.36 3217.13,3610.36 3311.31,3610.36 3722.13,3610.36 3816.31,3610.36 4227.13,3610.36 4321.31,3610.36 4732.13,3610.36 4826.31,3610.36 5237.13,3610.36 2862.54,3621.55 3160.9,3621.55 3367.54,3621.55 3665.9,3621.55 3872.54,3621.55 4170.9,3621.55 4377.54,3621.55 4675.9,3621.55 4882.54,3621.55 5180.9,3621.55 3220.6,3629.62 3725.6,3629.62 4230.6,3629.62 4735.6,3629.62 5240.6,3629.62 2803.3,3630.69 3308.3,3630.69 3813.3,3630.69 4318.3,3630.69 4823.3,3630.69 2802.29,3651.22 2859.61,3651.22 3163.83,3651.22 3221.15,3651.22 3307.29,3651.22 3364.61,3651.22 3668.83,3651.22 3726.15,3651.22 3812.29,3651.22 3869.61,3651.22 4173.83,3651.22 4231.15,3651.22 4317.29,3651.22 4374.61,3651.22 4678.83,3651.22 4736.15,3651.22 4822.29,3651.22 4879.61,3651.22 5183.83,3651.22 5241.15,3651.22 2803.3,3671.75 3220.14,3671.75 3308.3,3671.75 3725.14,3671.75 3813.3,3671.75 4230.14,3671.75 4318.3,3671.75 4735.14,3671.75 4823.3,3671.75 5240.14,3671.75 2863.04,3679.95 3368.04,3679.95 3873.04,3679.95 4378.04,3679.95 4883.04,3679.95 3160.9,3680.9 3665.9,3680.9 4170.9,3680.9 4675.9,3680.9 5180.9,3680.9 2806.31,3692.08 3217.13,3692.08 3311.31,3692.08 3722.13,3692.08 3816.31,3692.08 4227.13,3692.08 4321.31,3692.08 4732.13,3692.08 4826.31,3692.08 5237.13,3692.08 2871.19,3709.43 3152.25,3709.43 3376.19,3709.43 3657.25,3709.43 3881.19,3709.43 4162.25,3709.43 4386.19,3709.43 4667.25,3709.43 4891.19,3709.43 5172.25,3709.43 2811.31,3712.02 3212.14,3712.02 3316.31,3712.02 3717.14,3712.02 3821.31,3712.02 4222.14,3712.02 4326.31,3712.02 4727.14,3712.02 4831.31,3712.02 5232.14,3712.02 2818.23,3731.37 3205.9,3731.15 3323.23,3731.37 3710.9,3731.15 3828.23,3731.37 4215.9,3731.15 4333.23,3731.37 4720.9,3731.15 4838.23,3731.37 5225.9,3731.15 2885.25,3735.73 3138.19,3735.73 3390.25,3735.73 3643.19,3735.73 3895.25,3735.73 4148.19,3735.73 4400.25,3735.73 4653.19,3735.73 4905.25,3735.73 5158.19,3735.73 2827.02,3749.95 3196.42,3749.95 3332.02,3749.95 3701.42,3749.95 3837.02,3749.95 4206.42,3749.95 4342.02,3749.95 4711.42,3749.95 4847.02,3749.95 5216.42,3749.95 2904.17,3758.78 3119.28,3758.78 3409.17,3758.78 3624.28,3758.78 3914.17,3758.78 4129.28,3758.78 4419.17,3758.78 4924.17,3758.78 5139.28,3758.78 4635,3760 2837.58,3767.58 3185.86,3767.58 3342.58,3767.58 3690.86,3767.58 3847.58,3767.58 4195.86,3767.58 4352.58,3767.58 4700.86,3767.58 4857.58,3767.58 5205.86,3767.58 2927.21,3777.69 3096.23,3777.69 3432.21,3777.69 3601.23,3777.69 3937.21,3777.69 4106.23,3777.69 4442.21,3777.69 4611.23,3777.69 4947.21,3777.69 5116.23,3777.69 2849.83,3784.08 3173.61,3784.08 3354.83,3784.08 3678.61,3784.08 3859.83,3784.08 4183.61,3784.08 4364.83,3784.08 4688.61,3784.08 4869.83,3784.08 5193.61,3784.08 2953.51,3791.75 3069.93,3791.75 3458.51,3791.75 3574.93,3791.75 3963.51,3791.75 4079.93,3791.75 4468.51,3791.75 4584.93,3791.75 4973.51,3791.75 5089.93,3791.75 3159.81,3799.31 3664.81,3799.31 4169.81,3799.31 4674.81,3799.31 5179.81,3799.31 2982.05,3800.4 3041.4,3800.4 3487.05,3800.4 3546.4,3800.4 3992.05,3800.4 4051.4,3800.4 4497.05,3800.4 4556.4,3800.4 5002.05,3800.4 5061.4,3800.4 2862.23,3800.59 3367.23,3800.59 3872.23,3800.59 4377.23,3800.59 4882.23,3800.59 3144.58,3813.11 3649.58,3813.11 4154.58,3813.11 4659.58,3813.11 5164.58,3813.11 2878.77,3814.07 3383.77,3814.07 3888.77,3814.07 4393.77,3814.07 4898.77,3814.07 2895.37,3825.36 3128.08,3825.36 3400.37,3825.36 3633.08,3825.36 3905.37,3825.36 4138.08,3825.36 4410.37,3825.36 4643.08,3825.36 4915.37,3825.36 5148.08,3825.36 2912.99,3835.92 3110.45,3835.92 3417.99,3835.92 3615.45,3835.92 3922.99,3835.92 4120.45,3835.92 4427.99,3835.92 4625.45,3835.92 4932.99,3835.92 5130.45,3835.92 2931.57,3844.71 3091.87,3844.71 3436.57,3844.71 3596.87,3844.71 3941.57,3844.71 4101.87,3844.71 4446.57,3844.71 4606.87,3844.71 4951.57,3844.71 5111.87,3844.71 2950.93,3851.64 3072.52,3851.64 3455.93,3851.64 3577.52,3851.64 3960.93,3851.64 4082.52,3851.64 4465.93,3851.64 4587.52,3851.64 4970.93,3851.64 5092.52,3851.64 2970.86,3856.63 3052.58,3856.63 3475.86,3856.63 3557.58,3856.63 3980.86,3856.63 4062.58,3856.63 4485.86,3856.63 4567.58,3856.63 4990.86,3856.63 5072.58,3856.63 2970.86,3950.81 3052.58,3950.81 3475.86,3950.81 3557.58,3950.81 3980.86,3950.81 4062.58,3950.81 4485.86,3950.81 4567.58,3950.81 4990.86,3950.81 5072.58,3950.81 2950.93,3955.81 3455.93,3955.81 3960.93,3955.81 4465.93,3955.81 4970.93,3955.81 3073.01,3957.21 3578.01,3957.21 4083.01,3957.21 4588.01,3957.21 5093.01,3957.21 2931.57,3962.73 3091.87,3962.73 3436.57,3962.73 3596.87,3962.73 3941.57,3962.73 4101.87,3962.73 4446.57,3962.73 4606.87,3962.73 4951.57,3962.73 5111.87,3962.73 2974.61,3969.63 3479.61,3969.63 3984.61,3969.63 4489.61,3969.63 4994.61,3969.63 2911.98,3971.64 3110.45,3971.52 3416.98,3971.64 3615.45,3971.52 3921.98,3971.64 4120.45,3971.52 4426.98,3971.64 4625.45,3971.52 4931.98,3971.64 5130.45,3971.52 2895.37,3982.08 3128.08,3982.08 3400.37,3982.08 3633.08,3982.08 3905.37,3982.08 4138.08,3982.08 4410.37,3982.08 4643.08,3982.08 4915.37,3982.08 5148.08,3982.08 2950,3985 3455,3985 3960,3985 4465,3985 4970,3985 2978.23,3987.83 3483.23,3987.83 3988.23,3987.83 4493.23,3987.83 4998.23,3987.83 2878.86,3994.33 3144.58,3994.33 3383.86,3994.33 3649.58,3994.33 3888.86,3994.33 4154.58,3994.33 4393.86,3994.33 4659.58,3994.33 4898.86,3994.33 5164.58,3994.33 3011.72,4004.11 3516.72,4004.11 4021.72,4004.11 4526.72,4004.11 5031.72,4004.11 3041.4,4007.04 3546.4,4007.04 4051.4,4007.04 4556.4,4007.04 5061.4,4007.04 2863.63,4008.13 2981.13,4008.15 3159.81,4008.13 3368.63,4008.13 3486.13,4008.15 3664.81,4008.13 3873.63,4008.13 3991.13,4008.15 4169.81,4008.13 4378.63,4008.13 4496.13,4008.15 4674.81,4008.13 4883.63,4008.13 5001.13,4008.15 5179.81,4008.13 3069.84,4014.62 3574.84,4014.62 4079.84,4014.62 4584.84,4014.62 5089.84,4014.62 2953.51,4015.69 3458.51,4015.69 3963.51,4015.69 4468.51,4015.69 4973.51,4015.69 2849.83,4023.36 3173.61,4023.36 3354.83,4023.36 3678.61,4023.36 3859.83,4023.36 4183.61,4023.36 4364.83,4023.36 4688.61,4023.36 4869.83,4023.36 5193.61,4023.36 2927.21,4029.75 3096.23,4029.75 3432.21,4029.75 3601.23,4029.75 3937.21,4029.75 4106.23,4029.75 4442.21,4029.75 4611.23,4029.75 4947.21,4029.75 5116.23,4029.75 2837.58,4039.87 3185.86,4039.87 3342.58,4039.87 3690.86,4039.87 3847.58,4039.87 4195.86,4039.87 4352.58,4039.87 4700.86,4039.87 4857.58,4039.87 5205.86,4039.87 2904.17,4048.67 3119.28,4048.67 3409.17,4048.67 3624.28,4048.67 3914.17,4048.67 4129.28,4048.67 4419.17,4048.67 4634.28,4048.67 4924.17,4048.67 5139.28,4048.67 2827.02,4057.49 3332.02,4057.49 3837.02,4057.49 4342.02,4057.49 4847.02,4057.49 3194.83,4058.24 3699.83,4058.24 4204.83,4058.24 4709.83,4058.24 5214.83,4058.24 2885.25,4071.71 3138.19,4071.71 3390.25,4071.71 3643.19,4071.71 3895.25,4071.71 4148.19,4071.71 4400.25,4071.71 4653.19,4071.71 4905.25,4071.71 5158.19,4071.71 2818.23,4076.07 3205.21,4076.07 3323.23,4076.07 3710.21,4076.07 3828.23,4076.07 4215.21,4076.07 4333.23,4076.07 4720.21,4076.07 4838.23,4076.07 5225.21,4076.07 2811.31,4095.43 3212.14,4095.43 3316.31,4095.43 3717.14,4095.43 3821.31,4095.43 4222.14,4095.43 4326.31,4095.43 4727.14,4095.43 4831.31,4095.43 5232.14,4095.43 2871.19,4098.01 3152.25,4098.01 3376.19,4098.01 3657.25,4098.01 3881.19,4098.01 4162.25,4098.01 4386.19,4098.01 4667.25,4098.01 4891.19,4098.01 5172.25,4098.01 2806.31,4115.36 3217.13,4115.36 3311.31,4115.36 3722.13,4115.36 3816.31,4115.36 4227.13,4115.36 4321.31,4115.36 4732.13,4115.36 4826.31,4115.36 5237.13,4115.36 2862.54,4126.55 3160.9,4126.55 3367.54,4126.55 3665.9,4126.55 3872.54,4126.55 4170.9,4126.55 4377.54,4126.55 4675.9,4126.55 4882.54,4126.55 5180.9,4126.55 3220.6,4134.62 3725.6,4134.62 4230.6,4134.62 4735.6,4134.62 5240.6,4134.62 2803.3,4135.69 3308.3,4135.69 3813.3,4135.69 4318.3,4135.69 4823.3,4135.69 2802.29,4156.22 2859.61,4156.22 3163.83,4156.22 3221.15,4156.22 3307.29,4156.22 3364.61,4156.22 3668.83,4156.22 3726.15,4156.22 3812.29,4156.22 3869.61,4156.22 4173.83,4156.22 4231.15,4156.22 4317.29,4156.22 4374.61,4156.22 4678.83,4156.22 4736.15,4156.22 4822.29,4156.22 4879.61,4156.22 5183.83,4156.22 5241.15,4156.22 2803.3,4176.75 3220.14,4176.75 3308.3,4176.75 3725.14,4176.75 3813.3,4176.75 4230.14,4176.75 4318.3,4176.75 4735.14,4176.75 4823.3,4176.75 5240.14,4176.75 2863.04,4184.95 3368.04,4184.95 3873.04,4184.95 4378.04,4184.95 4883.04,4184.95 3160.9,4185.9 3665.9,4185.9 4170.9,4185.9 4675.9,4185.9 5180.9,4185.9 2806.31,4197.08 3217.13,4197.08 3311.31,4197.08 3722.13,4197.08 3816.31,4197.08 4227.13,4197.08 4321.31,4197.08 4732.13,4197.08 4826.31,4197.08 5237.13,4197.08 2871.19,4214.43 3152.25,4214.43 3376.19,4214.43 3657.25,4214.43 3881.19,4214.43 4162.25,4214.43 4386.19,4214.43 4667.25,4214.43 4891.19,4214.43 5172.25,4214.43 2811.31,4217.02 3212.14,4217.02 3316.31,4217.02 3717.14,4217.02 3821.31,4217.02 4222.14,4217.02 4326.31,4217.02 4727.14,4217.02 4831.31,4217.02 5232.14,4217.02 2818.23,4236.37 3205.9,4236.15 3323.23,4236.37 3710.9,4236.15 3828.23,4236.37 4215.9,4236.15 4333.23,4236.37 4720.9,4236.15 4838.23,4236.37 5225.9,4236.15 2885.25,4240.73 3138.19,4240.73 3390.25,4240.73 3643.19,4240.73 3895.25,4240.73 4148.19,4240.73 4400.25,4240.73 4653.19,4240.73 4905.25,4240.73 5158.19,4240.73 2827.02,4254.95 3196.42,4254.95 3332.02,4254.95 3701.42,4254.95 3837.02,4254.95 4206.42,4254.95 4342.02,4254.95 4711.42,4254.95 4847.02,4254.95 5216.42,4254.95 2904.17,4263.78 3119.28,4263.78 3409.17,4263.78 3624.28,4263.78 3914.17,4263.78 4129.28,4263.78 4419.17,4263.78 4634.28,4263.78 4924.17,4263.78 5139.28,4263.78 2837.58,4272.58 3185.86,4272.58 3342.58,4272.58 3690.86,4272.58 3847.58,4272.58 4195.86,4272.58 4352.58,4272.58 4700.86,4272.58 4857.58,4272.58 5205.86,4272.58 2927.21,4282.69 3096.23,4282.69 3432.21,4282.69 3601.23,4282.69 3937.21,4282.69 4106.23,4282.69 4442.21,4282.69 4611.23,4282.69 4947.21,4282.69 5116.23,4282.69 2849.83,4289.08 3173.61,4289.08 3354.83,4289.08 3678.61,4289.08 3859.83,4289.08 4183.61,4289.08 4364.83,4289.08 4688.61,4289.08 4869.83,4289.08 5193.61,4289.08 2953.51,4296.75 3069.93,4296.75 3458.51,4296.75 3574.93,4296.75 3963.51,4296.75 4079.93,4296.75 4468.51,4296.75 4584.93,4296.75 4973.51,4296.75 5089.93,4296.75 3159.81,4304.31 3664.81,4304.31 4169.81,4304.31 4674.81,4304.31 5179.81,4304.31 2982.05,4305.4 3041.4,4305.4 3487.05,4305.4 3546.4,4305.4 3992.05,4305.4 4051.4,4305.4 4497.05,4305.4 4556.4,4305.4 5002.05,4305.4 5061.4,4305.4 2862.23,4305.59 3367.23,4305.59 3872.23,4305.59 4377.23,4305.59 4882.23,4305.59 3144.58,4318.11 3649.58,4318.11 4154.58,4318.11 4659.58,4318.11 5164.58,4318.11 2878.77,4319.07 3383.77,4319.07 3888.77,4319.07 4393.77,4319.07 4898.77,4319.07 2895.37,4330.36 3128.08,4330.36 3400.37,4330.36 3633.08,4330.36 3905.37,4330.36 4138.08,4330.36 4410.37,4330.36 4643.08,4330.36 4915.37,4330.36 5148.08,4330.36 2912.99,4340.92 3110.45,4340.92 3417.99,4340.92 3615.45,4340.92 3922.99,4340.92 4120.45,4340.92 4427.99,4340.92 4625.45,4340.92 4932.99,4340.92 5130.45,4340.92 2931.57,4349.71 3091.87,4349.71 3436.57,4349.71 3596.87,4349.71 3941.57,4349.71 4101.87,4349.71 4446.57,4349.71 4606.87,4349.71 4951.57,4349.71 5111.87,4349.71 2950.93,4356.64 3072.52,4356.64 3455.93,4356.64 3577.52,4356.64 3960.93,4356.64 4082.52,4356.64 4465.93,4356.64 4587.52,4356.64 4970.93,4356.64 5092.52,4356.64 2970.86,4361.63 3052.58,4361.63 3475.86,4361.63 3557.58,4361.63 3980.86,4361.63 4062.58,4361.63 4485.86,4361.63 4567.58,4361.63 4990.86,4361.63 5072.58,4361.63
